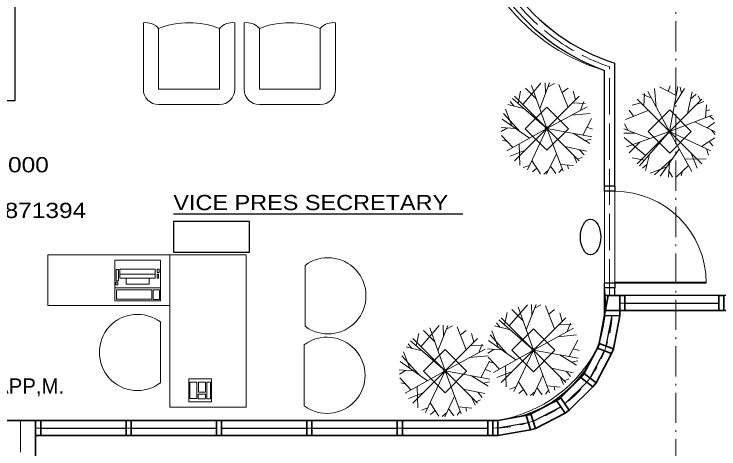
# Model space of a CAD drawing. Extents: x -118748 to -117136, y -118748 to -117596.
# Drawn here: x -118268.3 to -118046.3, y -118597 to -118460 of the extents above; entities that cross this region are included whole.
import ezdxf
from ezdxf.enums import TextEntityAlignment as Align

# ---------------------------------------------------------------- set-up
doc = ezdxf.new("R2010")
doc.units = 0
doc.header["$LTSCALE"] = 1.9
doc.header["$PDMODE"] = 32
doc.header["$PDSIZE"] = 0.95
for name, pattern in [('DOT_DASHED', [7.7, 5, -1.2, 0.3, -1.2]), ('LONG_DASHED', [7.5, 6, -1.5]), ('MEDIUM_DASHED', [4.5, 3, -1.5])]:
    doc.linetypes.add(name, pattern=pattern)
for name, color, linetype, lineweight in [('10', 7, 'DOT_DASHED', 13), ('15', 7, 'Continuous', 13), ('16', 7, 'Continuous', 13), ('17', 7, 'Continuous', 25), ('2', 7, 'Continuous', 35), ('23', 7, 'Continuous', 25), ('25', 7, 'Continuous', 13), ('26', 7, 'Continuous', 25), ('3', 7, 'Continuous', 35), ('30', 7, 'Continuous', 13), ('4', 7, 'Continuous', 35), ('42', 7, 'Continuous', 25), ('45', 7, 'Continuous', 25), ('5', 7, 'Continuous', 13), ('6', 7, 'Continuous', 13), ('60', 7, 'LONG_DASHED', 13), ('8', 7, 'MEDIUM_DASHED', 13), ('9', 7, 'Continuous', 35)]:
    doc.layers.add(name, color=color, linetype=linetype, lineweight=lineweight)
doc.layers.add('53', color=7, linetype='Continuous')

msp = doc.modelspace()

# ---------------------------------------------------------------- linework, layer by layer
at = {"layer": '10'}
msp.add_line((-118059.921, -117628.339), (-118059.921, -118698.41), dxfattribs=at)
at = {"layer": '15'}
for p, q in [((-118227.59, -118462.717), (-118227.59, -118483.702)), ((-118198.79, -118483.702), (-118198.79, -118462.717)), ((-118195.854, -118462.717), (-118195.854, -118483.702)), ((-118167.054, -118483.702), (-118167.054, -118462.717)), ((-118222.79, -118488.502), (-118203.59, -118488.502)), ((-118191.054, -118488.502), (-118171.854, -118488.502)), ((-118176.672, -118539.163), (-118176.672, -118558.363)), ((-118222.233, -118576.204), (-118222.233, -118557.004)), ((-118176.953, -118564.194), (-118176.953, -118583.394))]:
    msp.add_line(p, q, dxfattribs=at)
at = {"layer": '15', "lineweight": 25}
for p in [(-118271.121, -118588.01), (-118261.521, -118645.61)]:
    msp.add_line(p, (-118261.521, -118588.01), dxfattribs=at)
at = {"layer": '15'}
for points in [[(-118222.79, -118464.502), (-118222.79, -118483.702), (-118203.59, -118483.702), (-118203.59, -118464.502)], [(-118191.054, -118464.502), (-118191.054, -118483.702), (-118171.854, -118483.702), (-118171.854, -118464.502)]]:
    msp.add_lwpolyline(points, dxfattribs=at)
for points in [[(-118219.234, -118551.839), (-118219.234, -118535.839), (-118257.634, -118535.839), (-118257.634, -118551.839)], [(-118195.234, -118583.839), (-118195.234, -118535.839), (-118219.234, -118535.839), (-118219.234, -118583.839)]]:
    msp.add_lwpolyline(points, close=True, dxfattribs=at)
for centre, radius, start, end in [((-118226.895, -118468.194), 5.521, 41.96294, 97.22666), ((-118213.19, -118489.416), 26.699, 68.92678, 111.07322), ((-118199.484, -118468.194), 5.521, 82.77334, 138.03706), ((-118195.159, -118468.194), 5.521, 41.96294, 97.22666), ((-118181.454, -118489.416), 26.699, 68.92678, 111.07322), ((-118167.748, -118468.194), 5.521, 82.77334, 138.03706), ((-118222.79, -118483.702), 4.8, 180, 270), ((-118203.59, -118483.702), 4.8, 270, 0), ((-118191.054, -118483.702), 4.8, 180, 270), ((-118171.854, -118483.702), 4.8, 270, 0), ((-118169.472, -118548.763), 12, 233.13011, 126.8699), ((-118229.433, -118566.604), 12, 53.1301, 306.8699), ((-118169.753, -118573.794), 12, 233.13011, 126.8699)]:
    msp.add_arc(centre, radius, start, end, dxfattribs=at)
at = {"layer": '16'}
msp.add_line((-118236.615, -118546.289), (-118222.215, -118546.289), dxfattribs=at)
for points in [[(-118236.615, -118550.289), (-118236.615, -118537.49), (-118222.215, -118537.49), (-118222.215, -118550.289)], [(-118236.157, -118544.007), (-118236.157, -118540.47), (-118235.45, -118540.47), (-118235.45, -118544.007)], [(-118234.95, -118541.968), (-118234.95, -118540.368), (-118223.841, -118540.368), (-118223.841, -118541.968)], [(-118223.217, -118540.387), (-118223.217, -118541.386), (-118222.635, -118541.386), (-118222.635, -118540.387)], [(-118234.95, -118543.175), (-118234.95, -118541.968), (-118223.841, -118541.968), (-118223.841, -118543.175)], [(-118233.036, -118545.047), (-118233.036, -118543.175), (-118225.714, -118543.175), (-118225.714, -118545.047)], [(-118223.217, -118541.968), (-118223.217, -118543.216), (-118222.801, -118543.216), (-118222.801, -118541.968)], [(-118236.24, -118545.255), (-118236.24, -118544.423), (-118235.574, -118544.423), (-118235.574, -118545.255)], [(-118236.074, -118546.836), (-118236.074, -118549.832), (-118224.881, -118549.832), (-118224.881, -118546.836)], [(-118224.465, -118546.919), (-118224.465, -118549.873), (-118222.468, -118549.873), (-118222.468, -118546.919)], [(-118206.091, -118574.944), (-118206.091, -118582.144), (-118213.291, -118582.144), (-118213.291, -118574.944)], [(-118210.71, -118581.109), (-118210.71, -118575.992), (-118212.916, -118575.992), (-118212.916, -118581.109)], [(-118207.964, -118579.071), (-118207.964, -118575.95), (-118210.253, -118575.95), (-118210.253, -118579.071)], [(-118207.548, -118575.95), (-118207.548, -118581.193), (-118206.466, -118581.193), (-118206.466, -118575.95)], [(-118208.048, -118581.193), (-118208.048, -118579.736), (-118210.336, -118579.736), (-118210.336, -118581.193)]]:
    msp.add_lwpolyline(points, close=True, dxfattribs=at)
at = {"layer": '17'}
msp.add_line((-118218.139, -118522.975), (-118126.939, -118522.975), dxfattribs=at)
at = {"layer": '2'}
msp.add_lwpolyline([(-118077.526, -118548.633), (-118077.526, -118553.358), (-118082.334, -118553.358), (-118082.334, -118548.633)], close=True, dxfattribs=at)
at = {"layer": '23'}
for p, q in [((-118267.921, -118487.21), (-118267.921, -118346.41)), ((-118079.134, -118514.233), (-118079.134, -118475.475)), ((-118082.334, -118514.233), (-118082.334, -118477.77)), ((-118301.521, -118487.21), (-118267.921, -118487.21)), ((-118079.134, -118514.233), (-118082.334, -118514.233)), ((-118079.134, -118546.233), (-118082.334, -118546.233)), ((-118082.334, -118548.633), (-118082.334, -118546.233)), ((-118079.134, -118548.633), (-118079.134, -118546.233)), ((-118082.334, -118548.633), (-118079.134, -118548.633))]:
    msp.add_line(p, q, dxfattribs=at)
for radius, start, end in [(66.454, 180.01043, 250.28947), (63.254, 180, 252.31759)]:
    msp.add_arc((-118059.921, -118415.21), radius, start, end, dxfattribs=at)
at = {"layer": '25', "lineweight": 40}
msp.add_line((-118050.334, -118544.633), (-118079.134, -118544.633), dxfattribs=at)
at = {"layer": '25'}
msp.add_arc((-118079.134, -118544.633), 28.8, 359.99998, 89.99998, dxfattribs=at)
at = {"layer": '26'}
for points in [[(-118079.134, -118514.233), (-118079.134, -118515.833), (-118082.334, -118515.833), (-118082.334, -118514.233)], [(-118082.334, -118546.233), (-118082.334, -118544.633), (-118079.134, -118544.633), (-118079.134, -118546.233)]]:
    msp.add_lwpolyline(points, dxfattribs=at)
at = {"layer": '3'}
msp.add_lwpolyline([(-117890.316, -118553.433), (-118075.926, -118553.433), (-118077.534, -118553.433), (-118077.559, -118555.032), (-118079.538, -118565.426), (-118080.102, -118566.923), (-118085.022, -118576.169), (-118086.007, -118577.43), (-118093.457, -118584.791), (-118094.773, -118585.701), (-118104.079, -118590.508), (-118105.606, -118590.985), (-118115.921, -118592.801), (-118119.121, -118592.81), (-118261.521, -118592.81), (-118261.521, -118645.61), (-118506.321, -118645.61), (-118506.321, -118352.81), (-118595.921, -118352.81)], dxfattribs=at)
at = {"layer": '30'}
for p, q in [((-118108.098, -118488.47), (-118102.36, -118481.769)), ((-118102.765, -118489.727), (-118099.662, -118481.676)), ((-118100.981, -118485.098), (-118101.071, -118481.661)), ((-118100.14, -118482.917), (-118098.137, -118481.849)), ((-118103.833, -118486.724), (-118107.243, -118483.318)), ((-118100.517, -118496.051), (-118105.341, -118482.483)), ((-118093.848, -118489.382), (-118096.684, -118482.17)), ((-118095.684, -118484.714), (-118093.814, -118483.306)), ((-118066.079, -118489.278), (-118066.619, -118483.405)), ((-118059.806, -118485.679), (-118065.008, -118482.947)), ((-118062.298, -118484.37), (-118061.706, -118482.605)), ((-118061.881, -118497.004), (-118059.286, -118482.839)), ((-118060.362, -118488.712), (-118057.127, -118483.411)), ((-118058.067, -118484.951), (-118058.478, -118483.012)), ((-118090.334, -118506.233), (-118110.699, -118485.868)), ((-118110.699, -118506.233), (-118090.334, -118485.868)), ((-118109.584, -118488.128), (-118108.809, -118484.278)), ((-118091.44, -118486.974), (-118092.205, -118484.291)), ((-118067.664, -118486.36), (-118070.346, -118485.355)), ((-118069.944, -118488.941), (-118069.797, -118484.975)), ((-118061.881, -118497.004), (-118068.755, -118484.35)), ((-118056.176, -118491.299), (-118054.739, -118484.499)), ((-118055.201, -118486.683), (-118053.535, -118485.269)), ((-118052.17, -118487.292), (-118052.826, -118485.807)), ((-118107.752, -118489.729), (-118112.754, -118488.461)), ((-118110.936, -118488.921), (-118112.108, -118487.506)), ((-118100.517, -118496.051), (-118111.36, -118486.575)), ((-118092.454, -118487.988), (-118088.488, -118488.134)), ((-118089.873, -118490.268), (-118088.868, -118487.586)), ((-118070.958, -118487.926), (-118073.64, -118488.692)), ((-118051.699, -118486.821), (-118072.063, -118507.186)), ((-118051.699, -118507.186), (-118072.063, -118486.821)), ((-118053.387, -118488.51), (-118051.058, -118487.505)), ((-118050.559, -118492.702), (-118050.215, -118488.562)), ((-118111.587, -118495.2), (-118113.584, -118490.001)), ((-118100.517, -118496.051), (-118087.864, -118489.176)), ((-118068.549, -118490.335), (-118075.762, -118493.171)), ((-118073.217, -118492.17), (-118074.626, -118490.301)), ((-118050.375, -118490.489), (-118049.191, -118490.197)), ((-118106.023, -118499.14), (-118114.604, -118493.064)), ((-118108.892, -118497.108), (-118114.11, -118491.299)), ((-118092.791, -118491.853), (-118086.918, -118491.313)), ((-118089.192, -118498.126), (-118086.46, -118492.924)), ((-118061.881, -118497.004), (-118048.42, -118491.889)), ((-118049.217, -118492.192), (-118047.991, -118493.206)), ((-118075.015, -118496.627), (-118076.083, -118494.624)), ((-118053.95, -118493.99), (-118047.481, -118497.105)), ((-118050.032, -118495.877), (-118047.757, -118494.199)), ((-118110.404, -118496.038), (-118114.913, -118495.712)), ((-118112.95, -118495.854), (-118114.883, -118497.042)), ((-118100.517, -118496.051), (-118113.076, -118503.096)), ((-118100.517, -118496.051), (-118106.642, -118509.083)), ((-118100.517, -118496.051), (-118095.402, -118509.512)), ((-118100.517, -118496.051), (-118086.353, -118498.646)), ((-118087.883, -118495.634), (-118086.118, -118496.226)), ((-118072.834, -118497.468), (-118076.27, -118497.558)), ((-118068.204, -118499.252), (-118076.256, -118496.149)), ((-118061.881, -118497.004), (-118075.449, -118501.828)), ((-118061.881, -118497.004), (-118071.356, -118507.847)), ((-118061.881, -118497.004), (-118054.836, -118509.562)), ((-118061.881, -118497.004), (-118048.849, -118503.129)), ((-118048.655, -118496.54), (-118047.512, -118497.941)), ((-118111.214, -118502.051), (-118114.746, -118498.26)), ((-118112.984, -118500.151), (-118114.433, -118499.75)), ((-118092.226, -118497.57), (-118086.924, -118500.804)), ((-118088.464, -118499.865), (-118086.525, -118499.454)), ((-118069.462, -118504.585), (-118076.163, -118498.846)), ((-118051.828, -118501.729), (-118047.618, -118498.982)), ((-118109.25, -118500.95), (-118109.07, -118507.635)), ((-118094.812, -118501.756), (-118088.012, -118503.192)), ((-118071.208, -118500.32), (-118074.614, -118503.729)), ((-118049.398, -118500.144), (-118048.22, -118501.557)), ((-118107.363, -118502.897), (-118112.016, -118504.719)), ((-118097.503, -118503.981), (-118100.618, -118510.45)), ((-118090.197, -118502.731), (-118088.782, -118504.397)), ((-118058.792, -118502.51), (-118064.868, -118511.09)), ((-118055.035, -118503.849), (-118053.213, -118508.502)), ((-118050.27, -118502.461), (-118049.551, -118504.442)), ((-118105.242, -118506.104), (-118102.496, -118510.314)), ((-118092.023, -118504.545), (-118091.018, -118506.874)), ((-118090.806, -118505.762), (-118089.32, -118505.105)), ((-118069.804, -118506.07), (-118073.654, -118505.296)), ((-118068.203, -118504.238), (-118069.471, -118509.241)), ((-118060.824, -118505.379), (-118066.632, -118510.597)), ((-118056.982, -118505.737), (-118050.297, -118505.557)), ((-118105.974, -118507.662), (-118107.955, -118508.381)), ((-118103.657, -118508.534), (-118105.071, -118509.712)), ((-118099.39, -118507.9), (-118097.712, -118510.175)), ((-118096.215, -118507.373), (-118092.076, -118507.717)), ((-118094.002, -118507.557), (-118093.711, -118508.741)), ((-118069.01, -118507.423), (-118070.426, -118508.594)), ((-118062.732, -118508.074), (-118067.93, -118510.071)), ((-118061.894, -118506.891), (-118062.22, -118511.4)), ((-118055.88, -118507.7), (-118059.672, -118511.233)), ((-118100.053, -118509.277), (-118101.455, -118510.42)), ((-118095.705, -118508.715), (-118096.719, -118509.941)), ((-118062.078, -118509.437), (-118060.889, -118511.369)), ((-118057.781, -118509.471), (-118058.182, -118510.92)), ((-118112.342, -118558.254), (-118106.603, -118551.553)), ((-118104.76, -118565.835), (-118109.585, -118552.267)), ((-118107.009, -118559.511), (-118103.906, -118551.46)), ((-118105.225, -118554.882), (-118105.315, -118551.445)), ((-118104.384, -118552.701), (-118102.38, -118551.633)), ((-118098.092, -118559.166), (-118100.928, -118551.954)), ((-118113.827, -118557.912), (-118113.053, -118554.062)), ((-118108.077, -118556.508), (-118111.486, -118553.102)), ((-118099.927, -118554.498), (-118098.058, -118553.09)), ((-118095.683, -118556.758), (-118096.449, -118554.075)), ((-118115.18, -118558.705), (-118116.351, -118557.29)), ((-118104.76, -118565.835), (-118115.604, -118556.359)), ((-118094.578, -118576.017), (-118114.943, -118555.652)), ((-118114.943, -118576.017), (-118094.578, -118555.652)), ((-118094.117, -118560.052), (-118093.111, -118557.37)), ((-118140.161, -118564.855), (-118134.423, -118558.154)), ((-118135.896, -118563.109), (-118139.306, -118559.703)), ((-118132.58, -118572.436), (-118137.404, -118558.868)), ((-118134.828, -118566.113), (-118131.725, -118558.061)), ((-118133.044, -118561.483), (-118133.134, -118558.047)), ((-118132.203, -118559.302), (-118130.2, -118558.234)), ((-118125.911, -118565.768), (-118128.747, -118558.555)), ((-118127.747, -118561.1), (-118125.877, -118559.691)), ((-118111.995, -118559.513), (-118116.998, -118558.245)), ((-118104.76, -118565.835), (-118092.107, -118558.96)), ((-118096.697, -118557.772), (-118092.732, -118557.918)), ((-118141.646, -118564.513), (-118140.872, -118560.663)), ((-118123.502, -118563.359), (-118124.268, -118560.677)), ((-118113.136, -118566.892), (-118118.354, -118561.083)), ((-118115.831, -118564.984), (-118117.828, -118559.785)), ((-118097.035, -118561.637), (-118091.162, -118561.097)), ((-118142.999, -118565.307), (-118144.17, -118563.891)), ((-118132.58, -118572.436), (-118143.423, -118562.961)), ((-118122.397, -118582.618), (-118142.762, -118562.254)), ((-118142.762, -118582.618), (-118122.397, -118562.254)), ((-118121.936, -118566.653), (-118120.931, -118563.971)), ((-118110.267, -118568.924), (-118118.847, -118562.848)), ((-118093.436, -118567.91), (-118090.704, -118562.708)), ((-118139.815, -118566.114), (-118144.817, -118564.846)), ((-118132.58, -118572.436), (-118119.927, -118565.561)), ((-118124.517, -118564.373), (-118120.551, -118564.52)), ((-118114.647, -118565.822), (-118119.156, -118565.496)), ((-118117.194, -118565.638), (-118119.126, -118566.826)), ((-118104.76, -118565.835), (-118117.319, -118572.88)), ((-118104.76, -118565.835), (-118110.886, -118578.867)), ((-118104.76, -118565.835), (-118099.646, -118579.296)), ((-118104.76, -118565.835), (-118090.596, -118568.43)), ((-118092.127, -118565.418), (-118090.361, -118566.01)), ((-118140.955, -118573.493), (-118146.173, -118567.685)), ((-118143.65, -118571.585), (-118145.647, -118566.387)), ((-118124.854, -118568.238), (-118118.981, -118567.698)), ((-118115.457, -118571.835), (-118118.99, -118568.044)), ((-118096.469, -118567.354), (-118091.168, -118570.588)), ((-118138.086, -118575.525), (-118146.667, -118569.449)), ((-118121.255, -118574.511), (-118118.523, -118569.309)), ((-118117.227, -118569.935), (-118118.677, -118569.534)), ((-118113.494, -118570.734), (-118113.314, -118577.419)), ((-118092.708, -118569.649), (-118090.768, -118569.238)), ((-118142.467, -118572.423), (-118146.976, -118572.097)), ((-118145.013, -118572.239), (-118146.945, -118573.428)), ((-118132.58, -118572.436), (-118145.139, -118579.481)), ((-118132.58, -118572.436), (-118138.705, -118585.468)), ((-118132.58, -118572.436), (-118127.465, -118585.897)), ((-118132.58, -118572.436), (-118118.415, -118575.031)), ((-118119.946, -118572.019), (-118118.181, -118572.611)), ((-118111.606, -118572.681), (-118116.259, -118574.503)), ((-118099.055, -118571.54), (-118092.256, -118572.976)), ((-118094.44, -118572.515), (-118093.026, -118574.181)), ((-118143.276, -118578.437), (-118146.809, -118574.645)), ((-118124.289, -118573.955), (-118118.987, -118577.19)), ((-118101.747, -118573.765), (-118104.861, -118580.234)), ((-118096.266, -118574.329), (-118095.262, -118576.658)), ((-118095.049, -118575.546), (-118093.563, -118574.889)), ((-118145.047, -118576.536), (-118146.496, -118576.135)), ((-118141.313, -118577.335), (-118141.133, -118584.02)), ((-118120.527, -118576.25), (-118118.588, -118575.839)), ((-118110.218, -118577.446), (-118112.199, -118578.165)), ((-118109.486, -118575.888), (-118106.739, -118580.098)), ((-118100.458, -118577.157), (-118096.319, -118577.501)), ((-118098.246, -118577.341), (-118097.954, -118578.525)), ((-118139.426, -118579.282), (-118144.078, -118581.104)), ((-118126.875, -118578.141), (-118120.075, -118579.577)), ((-118122.26, -118579.116), (-118120.845, -118580.782)), ((-118107.9, -118578.318), (-118109.314, -118579.496)), ((-118104.296, -118579.061), (-118105.698, -118580.204)), ((-118103.634, -118577.684), (-118101.956, -118579.959)), ((-118099.948, -118578.499), (-118100.963, -118579.725)), ((-118129.566, -118580.367), (-118132.681, -118586.836)), ((-118124.086, -118580.93), (-118123.081, -118583.259)), ((-118122.869, -118582.147), (-118121.383, -118581.49)), ((-118138.037, -118584.047), (-118140.018, -118584.766)), ((-118137.305, -118582.489), (-118134.558, -118586.699)), ((-118128.278, -118583.758), (-118124.138, -118584.102)), ((-118126.065, -118583.942), (-118125.773, -118585.126)), ((-118135.72, -118584.919), (-118137.133, -118586.097)), ((-118132.116, -118585.662), (-118133.517, -118586.805)), ((-118131.453, -118584.285), (-118129.775, -118586.56)), ((-118127.768, -118585.1), (-118128.782, -118586.326))]:
    msp.add_line(p, q, dxfattribs=at)
for points in [[(-118100.513, -118502.904), (-118107.302, -118496.115), (-118100.513, -118489.327), (-118093.725, -118496.115)], [(-118055.028, -118497), (-118061.816, -118503.789), (-118068.605, -118497), (-118061.816, -118490.212)], [(-118104.757, -118572.688), (-118111.545, -118565.899), (-118104.757, -118559.111), (-118097.969, -118565.899)], [(-118132.576, -118579.289), (-118139.365, -118572.501), (-118132.576, -118565.712), (-118125.788, -118572.501)]]:
    msp.add_lwpolyline(points, close=True, dxfattribs=at)
for p in [(-118100.517, -118496.051), (-118061.881, -118497.004), (-118104.76, -118565.835), (-118132.58, -118572.436)]:
    msp.add_point(p, dxfattribs=at)
at = {"layer": '4'}
msp.add_lwpolyline([(-118496.721, -117964.01), (-118496.721, -118636.01), (-118271.121, -118636.01), (-118271.121, -118588.01), (-118115.969, -118588.01), (-118106.1, -118586.234), (-118096.66, -118581.314), (-118089.115, -118573.804), (-118084.156, -118564.399), (-118081.154, -118548.633), (-118079.134, -118548.633), (-117884.057, -118548.587), (-117881.646, -118565.336), (-117876.897, -118574.111), (-117869.271, -118581.538), (-117859.789, -118586.351), (-117850.271, -118588.01), (-117695.121, -118588.01), (-117695.121, -118636.01), (-117469.521, -118636.01), (-117469.521, -117964.01)], close=True, dxfattribs=at)
at = {"layer": '42'}
msp.add_ellipse((-118086.734, -118530.233), major_axis=(0, -5.6), ratio=0.571429, dxfattribs=at)
at = {"layer": '45'}
msp.add_lwpolyline([(-118218.139, -118525.375), (-118218.139, -118534.975), (-118194.139, -118534.975), (-118194.139, -118525.375)], close=True, dxfattribs=at)
at = {"layer": '5'}
for points in [[(-118115.969, -118588.01), (-118271.121, -118588.01), (-118271.121, -118636.01), (-118496.721, -118636.01), (-118496.721, -117964.01)], [(-118082.334, -118477.77), (-118082.358, -118554.958), (-118084.029, -118563.732), (-118084.594, -118565.229), (-118088.804, -118573.214), (-118089.789, -118574.475), (-118096.188, -118580.843), (-118097.504, -118581.753), (-118105.509, -118585.926), (-118107.036, -118586.403), (-118115.921, -118588.001), (-118301.521, -118588.01), (-118301.521, -118520.81), (-118301.521, -118487.21), (-118267.921, -118487.21), (-118267.921, -118346.41)], [(-117887.108, -118475.475), (-117887.108, -118548.633), (-118079.134, -118548.633), (-118079.133, -118475.475)], [(-117881.646, -118565.336), (-117884.057, -118548.587), (-118079.134, -118548.633), (-118081.154, -118548.633), (-118084.156, -118564.399)]]:
    msp.add_lwpolyline(points, dxfattribs=at)
for centre, radius, start, end in [((-118059.921, -118415.21), 66.454, 180.01043, 250.28947), ((-118059.921, -118415.21), 63.254, 180, 252.31759), ((-118123.046, -118545.236), 43.355, 279.39552, 333.76873)]:
    msp.add_arc(centre, radius, start, end, dxfattribs=at)
at = {"layer": '6'}
msp.add_line((-118082.334, -118477.77), (-118082.334, -118546.233), dxfattribs=at)
for points in [[(-118496.721, -118636.01), (-118496.721, -118487.21), (-118301.521, -118487.21), (-118267.921, -118487.21), (-118267.921, -118346.41), (-118126.375, -118346.41), (-118126.374, -118415.21)], [(-117887.108, -118475.475), (-117887.108, -118548.633), (-118079.134, -118548.633), (-118079.134, -118475.475)], [(-118119.121, -118588.01), (-118271.121, -118588.01), (-118271.121, -118636.01), (-118496.721, -118636.01)]]:
    msp.add_lwpolyline(points, dxfattribs=at)
for centre, radius, start, end in [((-118065.048, -118418.819), 61.432, 176.63131, 253.65813), ((-118060.069, -118415.317), 63.106, 179.90204, 252.41563), ((-118118.776, -118551.228), 36.783, 269.46309, 7.80443)]:
    msp.add_arc(centre, radius, start, end, dxfattribs=at)
at = {"layer": '60'}
for p, q in [((-118080.734, -118548.633), (-118080.734, -118476.633)), ((-118266.321, -118640.81), (-118266.321, -118588.01))]:
    msp.add_line(p, q, dxfattribs=at)
msp.add_arc((-118059.921, -118415.21), 64.854, 180, 251.28157, dxfattribs=at)
at = {"layer": '8'}
for p, q in [((-118077.526, -118551.033), (-117888.716, -118551.033)), ((-118261.521, -118590.41), (-118117.521, -118590.41))]:
    msp.add_line(p, q, dxfattribs=at)
msp.add_arc((-118117.521, -118552.81), 37.6, 270.00003, 359.10726, dxfattribs=at)
at = {"layer": '9', "lineweight": 13}
for p, q in [((-118075.926, -118548.633), (-117890.316, -118548.633)), ((-118084.029, -118563.732), (-118082.358, -118554.958)), ((-118079.538, -118565.426), (-118077.559, -118555.032)), ((-118075.926, -118553.433), (-117890.316, -118553.433)), ((-118088.804, -118573.214), (-118084.594, -118565.229)), ((-118085.022, -118576.169), (-118080.102, -118566.923)), ((-118096.188, -118580.843), (-118089.789, -118574.475)), ((-118093.457, -118584.791), (-118086.007, -118577.43)), ((-118105.509, -118585.926), (-118097.504, -118581.753)), ((-118104.079, -118590.508), (-118094.773, -118585.701)), ((-118259.921, -118588.01), (-118119.121, -118588.01)), ((-118115.921, -118588.001), (-118107.036, -118586.403)), ((-118259.921, -118592.81), (-118119.121, -118592.81)), ((-118115.921, -118592.801), (-118105.606, -118590.985))]:
    msp.add_line(p, q, dxfattribs=at)
at = {"layer": '9', "lineweight": 25}
for p, q in [((-118075.926, -118551.033), (-118046.324, -118551.033)), ((-118081.783, -118564.579), (-118079.959, -118554.995)), ((-118086.913, -118574.692), (-118082.348, -118566.076)), ((-118094.822, -118582.817), (-118087.898, -118575.953)), ((-118104.794, -118588.217), (-118096.138, -118583.727)), ((-118259.921, -118590.41), (-118233.041, -118590.41)), ((-118231.441, -118590.41), (-118204.561, -118590.41)), ((-118202.961, -118590.41), (-118176.081, -118590.41)), ((-118174.481, -118590.41), (-118147.601, -118590.41)), ((-118146.001, -118590.41), (-118119.121, -118590.41)), ((-118115.921, -118590.401), (-118106.321, -118588.694))]:
    msp.add_line(p, q, dxfattribs=at)
at = {"layer": '9'}
for points in [[(-118075.926, -118548.633), (-118077.526, -118548.633), (-118077.526, -118553.433), (-118075.926, -118553.433)], [(-118044.724, -118548.633), (-118046.324, -118548.633), (-118046.324, -118553.433), (-118044.724, -118553.433)], [(-118082.334, -118553.358), (-118082.358, -118554.958), (-118077.559, -118555.032), (-118077.534, -118553.433)], [(-118084.029, -118563.732), (-118084.594, -118565.229), (-118080.102, -118566.923), (-118079.538, -118565.426)], [(-118088.804, -118573.214), (-118089.789, -118574.475), (-118086.007, -118577.43), (-118085.022, -118576.169)], [(-118096.188, -118580.843), (-118097.504, -118581.753), (-118094.773, -118585.701), (-118093.457, -118584.791)], [(-118105.509, -118585.926), (-118107.036, -118586.403), (-118105.606, -118590.985), (-118104.079, -118590.508)], [(-118259.921, -118588.01), (-118261.521, -118588.01), (-118261.521, -118592.81), (-118259.921, -118592.81)], [(-118231.441, -118588.01), (-118233.041, -118588.01), (-118233.041, -118592.81), (-118231.441, -118592.81)], [(-118202.961, -118588.01), (-118204.561, -118588.01), (-118204.561, -118592.81), (-118202.961, -118592.81)], [(-118174.481, -118588.01), (-118176.081, -118588.01), (-118176.081, -118592.81), (-118174.481, -118592.81)], [(-118146.001, -118588.01), (-118147.601, -118588.01), (-118147.601, -118592.81), (-118146.001, -118592.81)], [(-118117.521, -118588.01), (-118119.121, -118588.01), (-118119.121, -118592.81), (-118117.521, -118592.81)], [(-118115.921, -118588.001), (-118117.521, -118588.001), (-118117.521, -118592.801), (-118115.921, -118592.801)]]:
    msp.add_lwpolyline(points, close=True, dxfattribs=at)

# ---------------------------------------------------------------- texts
at = {"layer": '17', "width": 1.15}
msp.add_text('VICE PRES SECRETARY', height=4.8, dxfattribs=at).set_placement((-118218.139, -118521.775))
at = {"layer": '45', "width": 1.2}
for s, p in [('3000', (-118265.928, -118509.857)), ('795.871394', (-118265.928, -118524.257))]:
    msp.add_text(s, height=4.8, dxfattribs=at).set_placement(p, align=Align.CENTER)
at = {"layer": '53'}
msp.add_text('SAPP,M.', height=4.8, dxfattribs=at).set_placement((-118278.564, -118579.582))

doc.saveas('drawing.dxf')
